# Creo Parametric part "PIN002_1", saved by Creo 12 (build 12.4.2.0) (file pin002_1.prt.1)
Units: Custom; MM, KILOGRAM, SECS

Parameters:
  PTC_WM_ITERATION = "0"
  PTC_WM_VERSION = "-.0"
  PTC_WM_LIFECYCLE_STATE = "In Work"
  PTC_WM_LIFECYCLE = "MO_CADDocument"
  PTC_WM_CREATED_BY = "Maximilian Roepper (Z0017RMS: MO)"
  PTC_WM_CREATED_ON = "18-Sep-26 11:36:42 AM"
  PTC_WM_MODIFIED_BY = "Maximilian Roepper (Z0017RMS: MO)"
  PTC_WM_MODIFIED_ON = "18-Sep-26 11:36:46 AM"
  PDMLINKNUMBER = "PDM000071455048"
  PTC_WM_NAME = "pin002_1.prt"
  PTC_WM_NUMBER = "PDM000071455048"

Other parameters: WEIGHT, WEIGHT_FACTOR, WEIGHT_ADD, _MASS_TEMP, _DIFF_TEMP, MC_ERRORS, SUPPLIER

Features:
  1. coordinate system
  2. datum plane "PRT_YZ"
  3. datum plane "PRT_XY"
  4. datum plane "PRT_XZ"
  5. coordinate system
  6. datum axis
  7. datum axis
  8. datum axis
  9. coordinate system
  10. imported feature

Other named items: PRT, SIEMENS_MO, DRW_VIEW_ORG, PRT_X, PRT_Y, PRT_Z, CS0, ROUGH_GROB

Layers: 00_STD_CSYS-KSYS, 01_STD_PLANES-EBENEN, 02_STD_AXES-ACHSEN, 03_STD_CSYS-KSYS, 24_IMPORT_FEAT-IMPORT_KE

Surfaces: 14 plane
